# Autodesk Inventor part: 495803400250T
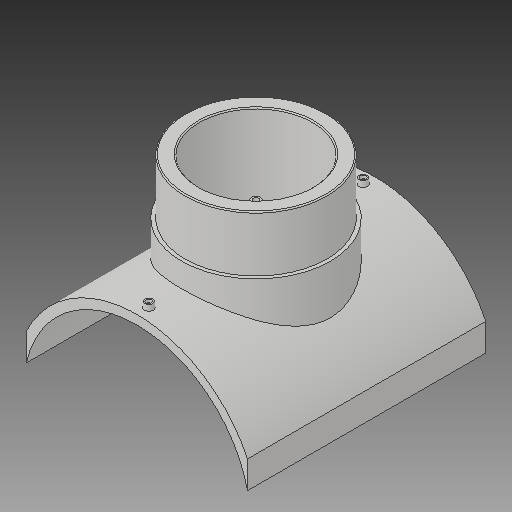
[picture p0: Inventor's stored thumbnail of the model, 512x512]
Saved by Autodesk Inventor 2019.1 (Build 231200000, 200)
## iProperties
Created: 2017-10
Part Number: 495803400250T
Material: Generic
Description: PLASSON BRANCH SADDLE 400x250
Document SubType Name: Modeling
Designer: KIM
Mass: 2754.05 g
Surface Area: 3037.44 cm^2
Volume: 2754.05 cm^3
Density: 1 g/cm^3
Appearance: Default
Author: KIM
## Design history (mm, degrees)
derived "495803.ipt"
feature "Solid1::495803.ipt"
tag "TaggingFeature1"
body "Solid1"
other parameters: "d1" = 16, "d4" = 0, "d12" = 225.6, "d13" = 14, "d14" = 189, "d16" = 5 deg, "d18" = 4, "d19" = 14, "d20" = 0, "d21" = 3, "d22" = 0, "d23" = 356, "d24" = 262.5, "d25" = 16, "d28" = 0, "d29" = 9.6, "d31" = 0, "d33" = 0, "d34" = 4, "d37" = 98, "d38" = 0, "d39" = 2, "x_" = 16, "D_" = 16
